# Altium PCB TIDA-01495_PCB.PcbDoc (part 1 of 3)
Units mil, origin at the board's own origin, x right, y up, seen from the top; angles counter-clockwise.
Board outline 7283.46 x 4330.71 mil, 2 copper layers (Top Layer, Bottom Layer), stack 64.6 mil thick; 242 components, 114 nets, 539 pads, 127 vias.
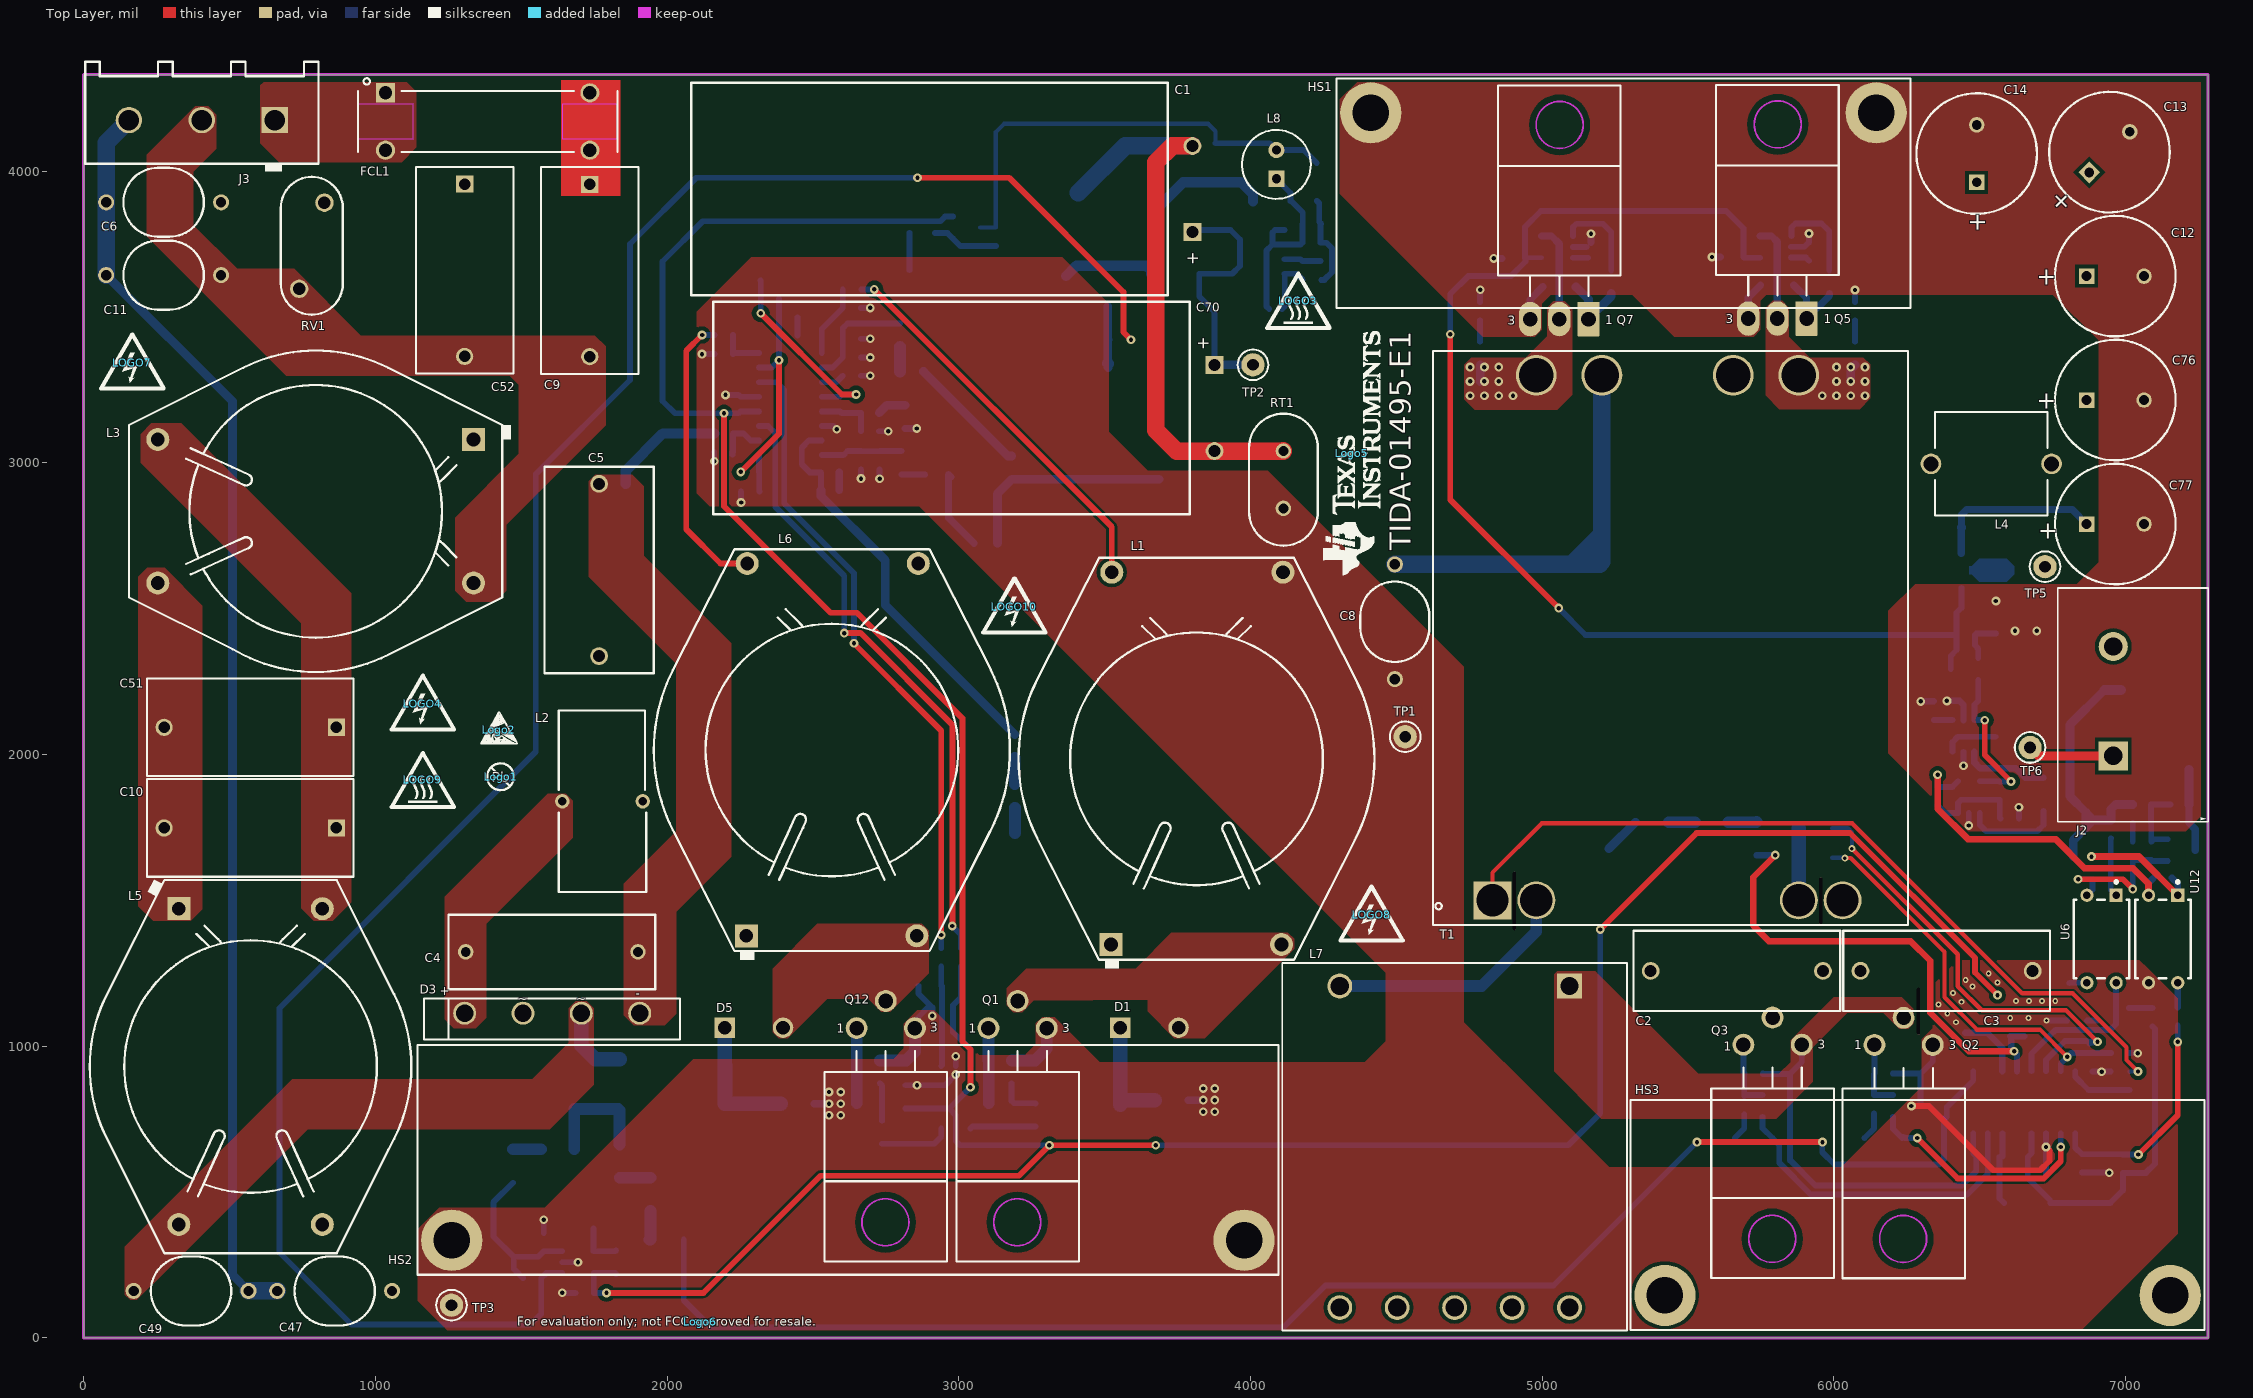
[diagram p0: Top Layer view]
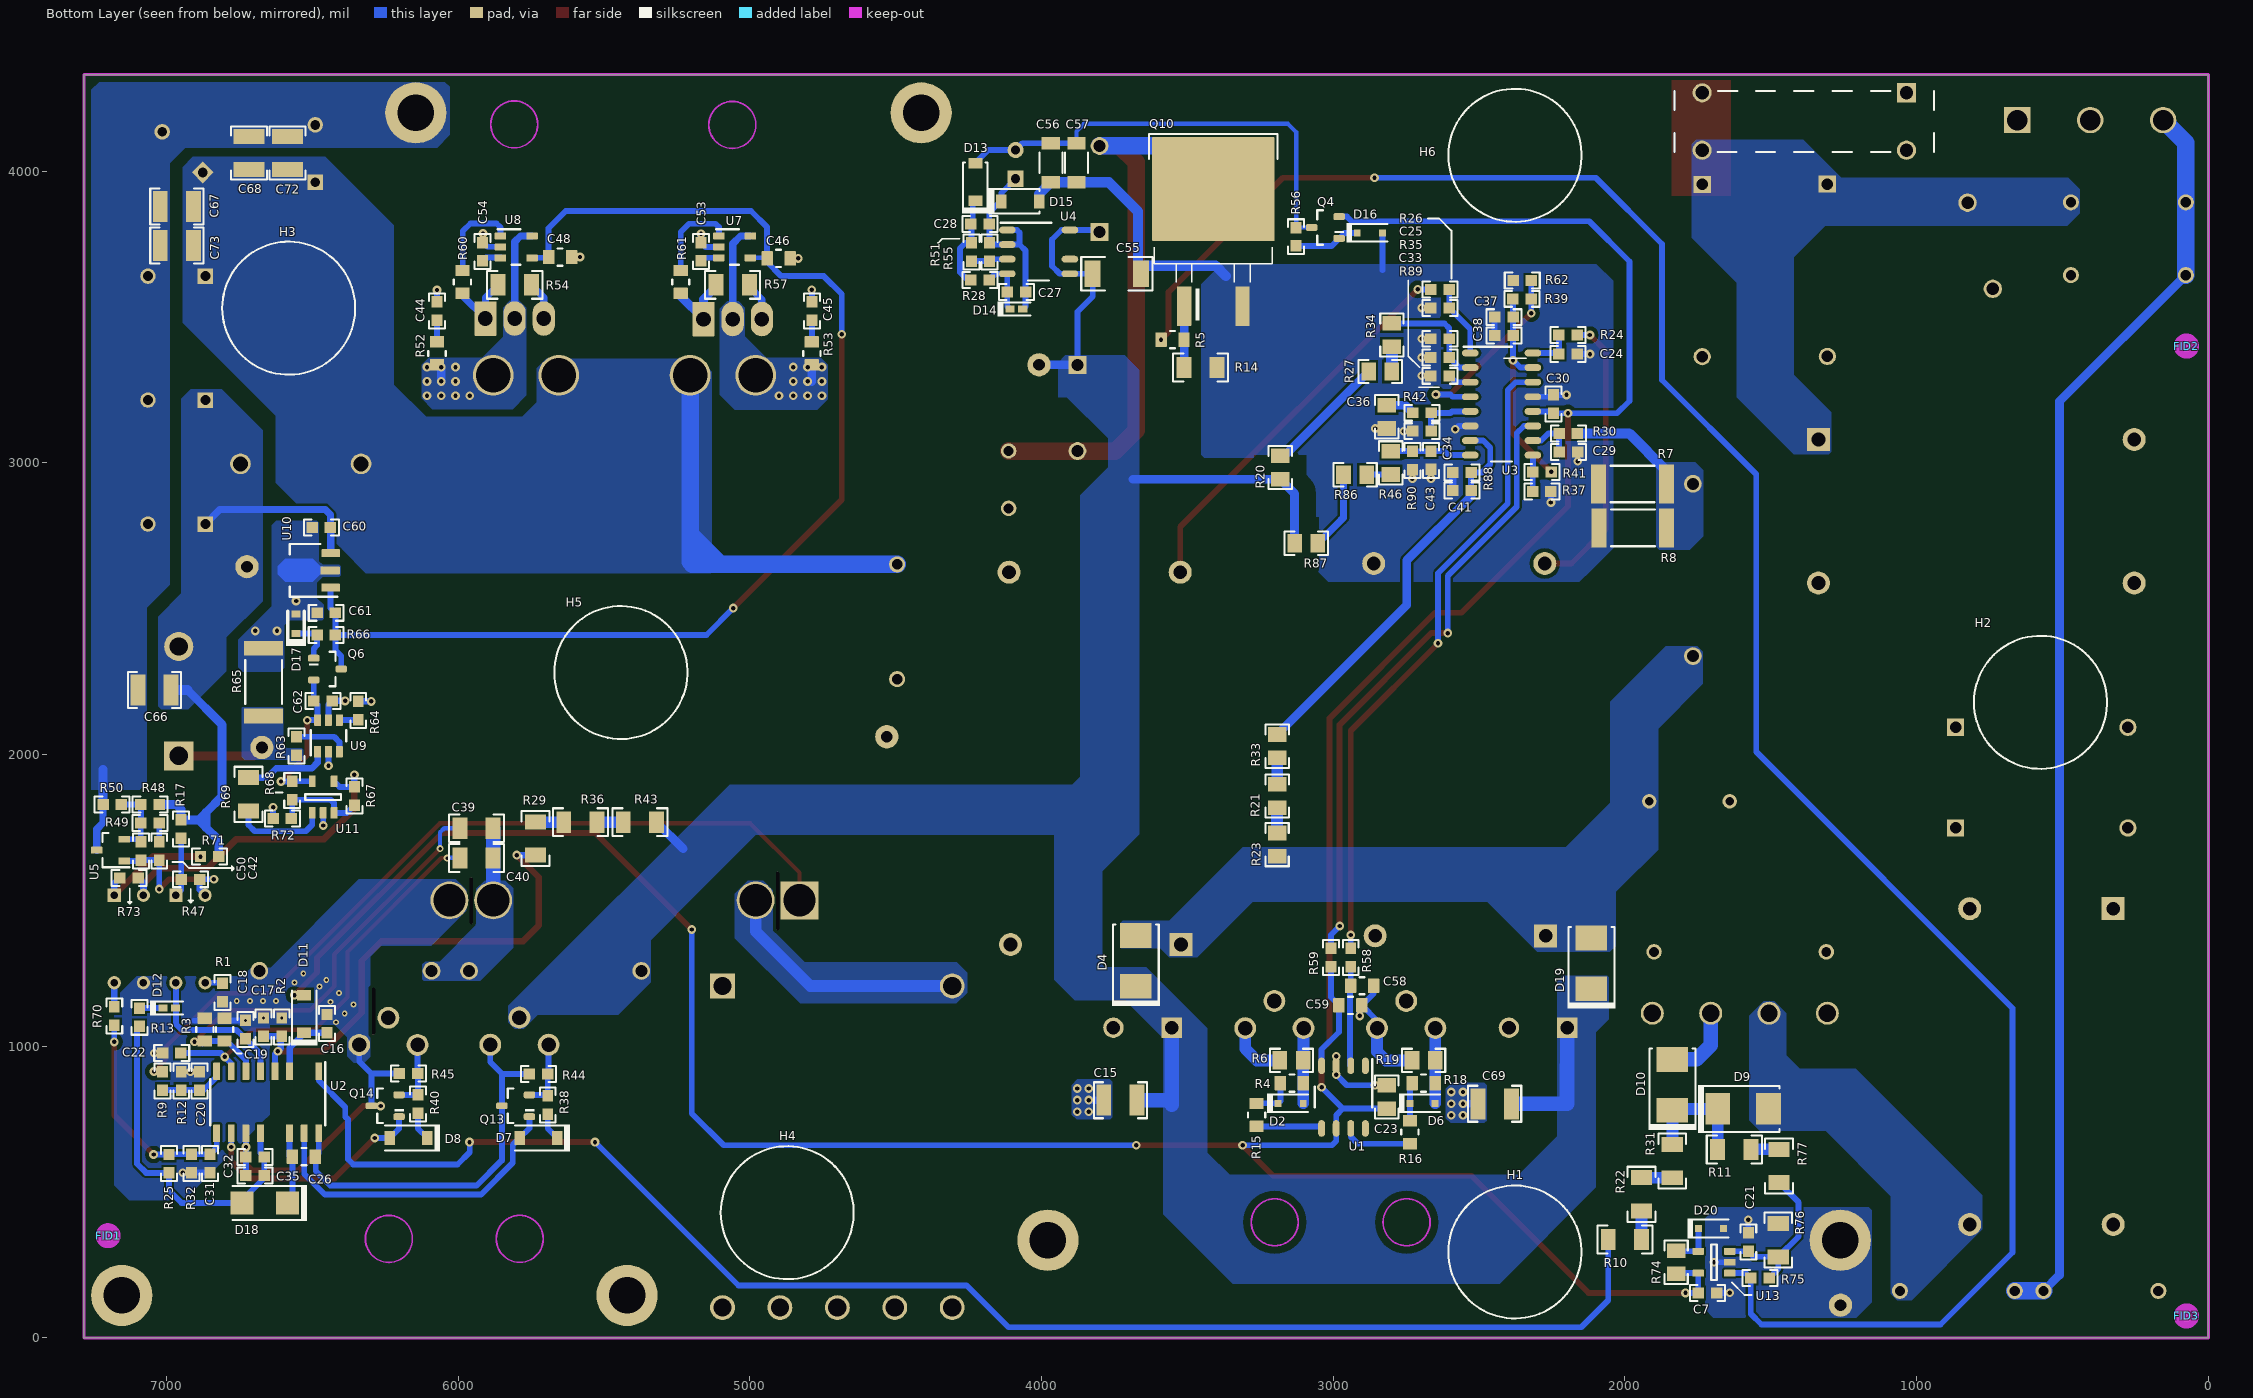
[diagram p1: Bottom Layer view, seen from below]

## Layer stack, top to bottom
Top Solder: solder mask 0.4, Solder Resist, Dk 3.5
Top Layer: signal copper 2.8
Dielectric1: core 59, FR-4 High Tg, Dk 4.8
Bottom Layer: signal copper 2.8
Bottom Solder: solder mask 0.4, Solder Resist, Dk 3.5

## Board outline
0,0 7283.46,0 7283.46,4330.71 0,4330.71

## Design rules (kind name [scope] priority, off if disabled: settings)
AcuteAngle [All] p1: minimum=4.50000000000000E+0001 checktracksonly=FALSE
AssemblyTestPointUsage [All] p1: valid=2
Clearance Clearance_1 [InNet('NetR10_2') vs InNet('PGND')] p1: gap=60 ignorepadtopadclearanceinfootprint=FALSE except(0: Arc-Hole Track-Hole SMDPad-Hole THPad-Hole Via-Hole Fill-Hole Poly-Hole Region-Hole Text-Hole)
Clearance Clearance_390V_Discrete [InNet('390V') vs InNet('NetR20_1') Or InNet('NetR86_2') Or InNet('NetQ3_1') Or InNet('SW') Or IsKeepOut] p2: gap=24 ignorepadtopadclearanceinfootprint=FALSE except(0: Arc-Hole Track-Hole SMDPad-Hole THPad-Hole Via-Hole Fill-Hole Poly-Hole Region-Hole Text-Hole)
Clearance Clearance_390V [InNet('390V')] p3: gap=59.05 ignorepadtopadclearanceinfootprint=FALSE except(0: Arc-Hole Track-Hole SMDPad-Hole THPad-Hole Via-Hole Fill-Hole Poly-Hole Region-Hole Text-Hole)
Clearance Clearance_MTG [InPadClass('MTG')] p4: gap=30 ignorepadtopadclearanceinfootprint=FALSE except(0: Arc-Hole Track-Hole SMDPad-Hole THPad-Hole Via-Hole Fill-Hole Poly-Hole Region-Hole Text-Hole)
Clearance Clearance_Keepouts [IsKeepOut] p5: gap=20 ignorepadtopadclearanceinfootprint=FALSE except(0: Arc-Hole Track-Hole SMDPad-Hole THPad-Hole Via-Hole Fill-Hole Poly-Hole Region-Hole Text-Hole; 19.5: Arc-SMDPad Track-SMDPad)
Clearance Clearance_Poly [InPolygon] p6: gap=15 ignorepadtopadclearanceinfootprint=FALSE except(0: Arc-Hole Track-Hole SMDPad-Hole THPad-Hole Via-Hole Fill-Hole Poly-Hole Region-Hole Text-Hole; 8: Track-Poly SMDPad-Poly; 12: THPad-Poly)
Clearance [All] p7: gap=7.7 ignorepadtopadclearanceinfootprint=FALSE except(0: Arc-Hole Track-Hole SMDPad-Hole THPad-Hole Via-Hole Fill-Hole Poly-Hole Region-Hole Text-Hole)
ComponentClearance ComponentClearance_MountingHoles_FiducialMarks [InComponentClass('Mounting Holes') vs InComponentClass('FiducialMark')] p1: gap=10 collisioncheckmode=3 verticalgap=10 showdistances=FALSE
ComponentClearance ComponentClearance_Shunt [InComponentClass('Header') vs InComponentClass('Shunt')] p2: gap=0 collisioncheckmode=3 verticalgap=0 showdistances=FALSE
ComponentClearance ComponentClearance_Logo [InComponentClass('Logo')] p3: gap=20 collisioncheckmode=3 verticalgap=10 showdistances=FALSE
ComponentClearance ComponentClearance_ScrewToNut [(HasFootprint('NY PMS 440 0025 PH')) vs (HasFootprint('Keystone_1902C'))] p4: gap=5 collisioncheckmode=3 verticalgap=10 showdistances=FALSE
ComponentClearance ComponentClearance_MountingHoles [InComponentClass('Mounting Holes')] p5: gap=50 collisioncheckmode=3 verticalgap=100000 showdistances=FALSE
ComponentClearance ComponentClearance_SmallPassives [HasFootprint('0201*') or HasFootprint('0402*') or HasFootprint('0508') or HasFootprint('0603*') or HasFootprint('0612') or HasFootprint('0805*') or HasFootprint('0815*') or HasFootprint('0830*') or HasFootprint('1206*') or HasFootprint('1210*') or HasFootprint('1808*') or HasFootprint('1812*') or HasFootprint('1825*') or HasFootprint('2010*') or HasFootprint('2220*') or HasFootprint('2225*') or HasFootprint('2512*') or HasFootprint('2728*') or HasFootprint('3518*') vs HasFootprint('0201*') or HasFootprint('0402*') or HasFootprint('0508') or HasFootprint('0603*') or HasFootprint('0612') or HasFootprint('0805*') or HasFootprint('0815*') or HasFootprint('0830*') or HasFootprint('1206*') or HasFootprint('1210*') or HasFootprint('1808*') or HasFootprint('1812*') or HasFootprint('1825*') or HasFootprint('2010*') or HasFootprint('2220*') or HasFootprint('2225*') or HasFootprint('2512*') or HasFootprint('2728*') or HasFootprint('3518*')] p6: gap=10 collisioncheckmode=3 verticalgap=10 showdistances=FALSE
ComponentClearance ComponentClearance_THtoSMT [IsThruComponent vs IsSMTComponent] p7: gap=5 collisioncheckmode=3 verticalgap=20 showdistances=FALSE
ComponentClearance ComponentClearance_THtoTH [IsThruComponent vs IsThruComponent] p8: gap=10 collisioncheckmode=3 verticalgap=10 showdistances=FALSE
ComponentClearance [All] p9: gap=10 collisioncheckmode=3 verticalgap=10 showdistances=FALSE
DiffPairsRouting [All] p1: maxlimit=100 minlimit=10 mostfreqgap=10 toplayer_minwidth=15 toplayer_maxwidth=15 toplayer_prefwidth=15 bottomlayer_minwidth=15 bottomlayer_maxwidth=15 bottomlayer_prefwidth=15 maxuncoupledlength=1000
FabricationTestPointUsage TestPointUsage [All] p1: valid=2 allowmultiple=FALSE
FabricationTestpoint Testpoint [All] p1: side=3 testpointundercomponent=TRUE minsize=40 maxsize=100 preferedsize=60 minholesize=0 maxholesize=40 preferedholesize=32 testpointgrid=1 allowsidetop=TRUE allowsidebottom=TRUE usegrid=TRUE gridtolerance=0.01
FanoutControl Fanout_LCC [IsLCC] p1: bgadir=Out bgaviamode=Centered fanoutstyle=Auto fanoutdirection=Alternating viagrid=1 // Fanout_LCC (Default Rule)
FanoutControl Fanout_BGA [IsBGA] p2: bgadir=Out bgaviamode=Centered fanoutstyle=Auto fanoutdirection=Alternating viagrid=1 // Fanout_BGA (Default Rule)
FanoutControl Fanout_Default [All] p4: bgadir=Out bgaviamode=Centered fanoutstyle=Auto fanoutdirection=Alternating viagrid=1 // Fanout_Default (Default Rule)
FanoutControl Fanout_Small [(CompPinCount < 5)] p5: bgadir=Out bgaviamode=Centered fanoutstyle=Auto fanoutdirection=OutThenIn viagrid=1 // Fanout_Small (Default Rule)
Height [All] p1: minheight=0 maxheight=2100 prefheight=500
HoleSize [All] p1: absolutevalues=TRUE maxlimit=251 minlimit=7.87 maxpercent=80.000 minpercent=20.000
MinimumAnnularRing MinimumAnnularRing_ThermalPadVias [IsVia and InAnyComponent] p1: minimumring=5.91
MinimumAnnularRing [All] p2: minimumring=5
MinimumSolderMaskSliver MinimumSolderMaskSliver_Logo [InComponentClass('Logo') vs InComponentClass('Logo')] p1: minsoldermaskwidth=0.7
MinimumSolderMaskSliver [All] p2: minsoldermaskwidth=3.94
PlaneConnect [All] p1: planeconnectstyle=Relief reliefexpansion=10 reliefentries=4 reliefconductorwidth=10 reliefairgap=10
PolygonConnect [All] p1: connectstyle=Direct reliefconductorwidth=10 reliefentries=4 polygonreliefangle="90 Angle" airgapwidth=10
RoutingVias [All] p1: holewidth=12 width=24 viastyle="Through Hole" minholewidth=7.87 minwidth=19.68 maxholewidth=40 maxwidth=65
RoutingVias ThermalPadVias [IsVia and InAnyComponent] p2: holewidth=7.87 width=19.68 viastyle="Through Hole" minholewidth=7.87 minwidth=19.68 maxholewidth=12.99 maxwidth=23.62
SilkToBoardRegionClearance [Not ((IsComment or IsDesignator) And (Hide <> 'False')) and not InRegion(1000,500,4000,800)] p1:
SilkToSilkClearance SilkToSilkClearance_Pb-FreeLogo [(HasFootprint('Pb-Free_Overlay_Medium') OR HasFootprint('Pb-Free_Overlay_Small')) vs (HasFootprint('Pb-Free_Overlay_Medium') OR HasFootprint('Pb-Free_Overlay_Small'))] p1: silktosilkclearance=0
SilkToSilkClearance [All] p2: silktosilkclearance=4
SilkToSolderMaskClearance SilkToComponentPadClearance [IsPad and InAnycomponent] p1: minsilkscreentomaskgap=5 clearancetoexposedcopper=TRUE
SilkToSolderMaskClearance "Silk to Solder Mask Opening" [All] p2: minsilkscreentomaskgap=4 clearancetoexposedcopper=FALSE
SolderMaskExpansion [All] p1: expansion=2.5
Width [All] p1: maxlimit=100 minlimit=6 preferedwidth=10 checkconnectedcopper=TRUE
14 further rules are at their usual default settings.

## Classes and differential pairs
component class AssemblyNote: ZZ1 ZZ2 ZZ3 ZZ4
component class FiducialMark: FID1 FID2 FID3
component class TIDA-01495_Hardware: FID1 FID2 FID3 H1 H2 H3 H4 H5 H6 Logo1 Logo2 LOGO3 LOGO4 Logo5 Logo6 LOGO7 LOGO8 LOGO9 LOGO10 ZZ1 ZZ2 ZZ3 ZZ4
component class Logo: Logo5
component class TIDA-01495-LLC: C2 C3 C8 C12 C13 C14 C16 C17 C18 C19 C20 C22 C26 C31 C32 C35 C39 C40 C42 C44 C45 C46 C48 C50 C53 C54 C60 C61 C62 C66 C67 C68 C72 C73 C76 C77 D7 D8 D11 D12 D17 D18 HS1 HS3 J2 L4 L7 Q2 Q3 Q5 Q6 Q7 Q13 Q14 R1 R2 R3 R9 R10 R12 R13 R17 R22 R25 R29 R31 R32 R36 R38 R40 R43 R44 R45 R47 R48 R49 R50 R52 R53 R54 R57 R60 R61 R63 R64 R65 R66 R67 R68 R69 R70 R71 R72 R73 T1 TP1 TP5 TP6 U2 U5 U6 U7 U8 U9 U10 U11 U12
component class TIDA-01495_PFC: C1 C4 C5 C6 C7 C9 C10 C11 C15 C21 C23 C24 C25 C27 C28 C29 C30 C33 C34 C36 C37 C38 C41 C43 C47 C49 C51 C52 C55 C56 C57 C58 C59 C69 C70 D1 D2 D3 D4 D5 D6 D9 D10 D13 D14 D15 D16 D19 D20 FCL1 HS2 J3 L1 L2 L3 L5 L6 L8 Q1 Q4 Q10 Q12 R4 R5 R6 R7 R8 R11 R14 R15 R16 R18 R19 R20 R21 R23 R24 R26 R27 R28 R30 R33 R34 R35 R37 R39 R41 R42 R46 R51 R55 R56 R58 R59 R62 R74 R75 R76 R77 R86 R87 R88 R89 R90 RT1 RV1 TP2 TP3 U1 U3 U4 U13
net class HV: 390V NetC2_2 NetC4_1 NetD1_3 NetD5_3 NetL7_2 NetR10_2 NetR20_1 NetR21_2 NetR86_2 SW VAC

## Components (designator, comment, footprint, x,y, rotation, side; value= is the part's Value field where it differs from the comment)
C1 "450BXW150MEFC18X45" KXG_1800X4000_HORIZONTALDOWN 3801.29,3938.37 r270 top value=150uF
C2 "B32642B0333J" B32652_1800x700x1250 5667.44,1258.06 r0 top value=0.033uF
C3 "B32642B0333J" B32652_1800x700x1250 6386.48,1258.16 r0 top value=0.033uF
C4 "450MPK474J" MPK_1800x650 1605,1323 r0 top value=0.47uF
C5 "450MPK105J" MPK_1800x950 1766.95,2632.53 r270 top value=1uF
C6 "AY2222M35Y5US63L7" CD45_700x600x1100 274,3893 r180 top value=2200pF
C7 "EMK107B7104KA-T" 0603 1717,154 r180 bottom value=0.1uF
C8 "AY2222M35Y5US63L7" CD45_700x600x1100 4495,2455 r270 top value=2200pF
C9 "B32922C3334K" B32922_14.5mm 1735,3659 r270 top value=0.33uF
C10 "B32922C3334K" B32922_14.5mm 571,1748 r180 top value=0.33uF
C11 "AY2222M35Y5US63L7" CD45_700x600x1100 274,3643.15 r0 top value=2200pF
C12 "35ZLH330MEFC10X12.5" Chemi-Con_1000x2000 6965,3640 r0 top value=330uF
C13 "35ZLH330MEFC10X12.5" Chemi-Con_1000x2000 6945,4065 r45 top value=330uF
C14 "35ZLH330MEFC10X12.5" Chemi-Con_1000x2000 6490,4060 r90 top value=330uF
C15 "VJ1210Y471KXEAT5Z" 1210 3729.56,814.56 r0 bottom value=470pF
C16 "0603ZD475KAT2A" 0603 6450,1077 r90 bottom value=4.7uF
C17 "06031C103JAT2A" 0603 6667,1065 r270 bottom value=0.01uF
C18 "C0603C101J5GAC" 0603 6729.53,1056.52 r90 bottom value=100pF
C19 "08055A3R3CAT2A" 0805_HV1 6801,1057 r90 bottom value=3.3pF
C20 "06035A100JAT2A" 0603 6886.38,881.04 r90 bottom value=10pF
C21 "EMK107B7104KA-T" 0603 1577,328 r90 bottom value=0.1uF
C22 "GRM188R71H682KA01D" 0603 6982,976 r0 bottom value=6800pF
C23 "0805YD225KAT2A" 0805_HV 2816.34,825.95 r90 bottom value=2.2uF
C24 "C0603C220J5GACTU" 0603 2194.93,3372.69 r180 bottom value=22pF
C25 "C0603C220J5GACTU" 0603 2633.73,3530.93 r0 bottom value=22pF
C26 "C0805C104K1RACTU" 0805_HV1 6529,621 r180 bottom value=0.1uF
C27 "C1608X5R1A106M" 0603 4086,3585 r180 bottom value=10uF
C28 "0603YC104JAT2A" 0603 4211,3819 r180 bottom value=0.1uF
C29 "C1608X7R1H102K" 0603 2193.11,3036.39 r180 bottom value=1000pF
C30 "GRM188R71E105KA12D" 0603 2245.41,3201.14 r90 bottom value=1uF
C31 "06033D224KAT2A" 0603 6850.46,597.77 r270 bottom value=0.22uF
C32 "GRM188R72A104KA35J" 0603 6696.34,620.01 r0 bottom value=0.1uF
C33 "C1608X7R1H102K" 0603 2633.82,3361.06 r0 bottom value=1000pF
C34 "06035A821JAT2A" 0603 2695.41,3108.33 r0 bottom value=820pF
C35 "0603ZD475KAT2A" 0603 6696.44,556.99 r0 bottom value=4.7uF
C36 "0805YD225KAT2A" 0805_HV 2816.35,3157.62 r270 bottom value=2.2uF
C37 "UMK107AB7105KA-T" 0603 2415.17,3499.14 r0 bottom value=1uF
C38 "EMK107B7104KA-T" 0603 2415.17,3436.5 r0 bottom value=0.1uF
C39 "GRM31A7U3A151JW31D" 1206 5937.28,1747 r0 bottom value=150pF
C40 "GRM31A7U3A151JW31D" 1206 5937.28,1645.3 r0 bottom value=150pF
C41 "06031C102MAT2A" 0603 2559.09,2905.14 r0 bottom value=1000pF
C42 "GRM188R71C473KA01D" 0603 7024.99,1669.6 r270 bottom value=0.047uF
C43 "GRM188R71H681KA01D" 0603 2664.81,3008.54 r270 bottom value=680pF
C44 "GRM1885C2A331JA01D" 0603 6072.63,3519.92 r270 bottom value=330pF
C45 "GRM1885C2A331JA01D" 0603 4787.51,3520.02 r270 bottom value=330pF
C46 "C0805C105K3RACTU" 0805_HV1 4901.4,3700.57 r180 bottom value=1uF
C47 "DE2E3KY222MA2BM01" CD45_700x600x1100 860.28,160.67 r180 top value=2200pF
C48 "C0805C105K3RACTU" 0805_HV1 5650.72,3705.36 r180 bottom value=1uF
C49 "DE2E3KY222MA2BM01" CD45_700x600x1100 368.12,160.67 r180 top value=2200pF
C50 "06035A100JAT2A" 0603 7087.99,1669.6 r270 bottom value=10pF
C51 "B32922C3334K" B32922_14.5mm 571,2093 r180 top value=0.33uF
C52 "B32922C3334K" B32922_14.5mm 1306,3660 r270 top value=0.33uF
C53 "C1608X6S1C225K080AC" 0603 5167.61,3723.64 r90 bottom value=2.2uF
C54 "C1608X6S1C225K080AC" 0603 5916,3723.64 r90 bottom value=2.2uF
C55 "VJ1808Y103KBLAT4X" 1808 3742,3648 r180 bottom value=0.01uF
C56 "C3216X5R1V226M160AC" 1206_180 3968,4028.43 r270 bottom value=22uF
C57 "C3216X5R1V226M160AC" 1206_180 3880.32,4028.43 r270 bottom value=22uF
C58 "08055A101JAT2A" 0805_HV1 2901,1207 r180 bottom value=100pF
C59 "08055A101JAT2A" 0805_HV1 2941,1140 r180 bottom value=100pF
C60 "GRM188R71E105KA12D" 0603 6469.26,2777.84 r0 bottom value=1uF
C61 "GRM188R71E105KA12D" 0603 6452.38,2485.72 r0 bottom value=1uF
C62 "GRM188R71E105KA12D" 0603 6463.53,2183.57 r180 bottom value=1uF
C66 "C3225X7S2A475K200AE" 1210 7041,2221 r0 bottom value=4.7uF
C67 "C3225X7S2A475K200AE" 1210 6964.44,3879.15 r0 bottom value=4.7uF
C68 "C3225X7S2A475K200AE" 1210 6717.47,4062.05 r90 bottom value=4.7uF
C69 "VJ1210Y471KXEAT5Z" 1210 2446.57,802.49 r0 bottom value=470pF
C70 "450BXW150MEFC18X45" KXG_1800x4000_horizontalDown 3877,3187.94 r270 top value=150uF
C72 "C3225X7S2A475K200AE" 1210 6585.37,4062.05 r90 bottom value=4.7uF
C73 "C3225X7S2A475K200AE" 1210 6964.44,3745.45 r0 bottom value=4.7uF
C76 "35ZLH330MEFC10X12.5" Chemi-Con_1000x2000 6965,3215 r0 top value=330uF
C77 "35ZLH330MEFC10X12.5" Chemi-Con_1000x2000 6965,2790 r0 top value=330uF
D1 "MUR860G" TO-220AC_HORIZ 3653.7,1063.35 r180 top value=0.98V
D2 "BAT54HT1G" sod-323 3146,804 r180 bottom value=0.35V
D3 "GBU8J" GBU 1606,1112.85 r0 top
D4 "RS1MB-13-F" SMB 3676.72,1292.22 r90 bottom value=1000V
D5 "MUR860G" TO-220AC_HORIZ 2297.66,1063.35 r180 top value=0.98V
D6 "BAT54HT1G" sod-323 2694,804 r180 bottom value=0.35V
D7 "SD103BW-7-F" SOD-123 5725,685 r0 bottom value=30V
D8 "SD103BW-7-F" SOD-123 6170,685 r0 bottom value=30V
D9 "RS1MB-13-F" SMB 1594.68,784.65 r180 bottom value=1000V
D10 "RS1MB-13-F" SMB 1836.97,867.36 r90 bottom value=1000V
D11 "SD103BW-7-F" SOD-123 6528,1110 r90 bottom value=30V
D12 "BZT52C6V2T-7" SOD-523 6990.8,1130.97 r180 bottom value=6.2V
D13 "UFM15PL-TP" SOD-123FL 4227.09,3962.99 r90 bottom value=600V
D14 "5.61V" SOD-523 4086,3527 r180 bottom
D15 "UFM15PL-TP" SOD-123FL 4073.11,3896.42 r180 bottom value=600V
D16 "BZX384-C15,115" sod-323 2874.34,3788.33 r180 bottom value=15V
D17 "CZRU52C5V6" SOD-523F 6555.94,2447.67 r90 bottom value=5.6V
D18 "US1J-13-F" SMA 6663.13,461.95 r0 bottom value=600V
D19 "RS1MB-13-F" SMB 2114.75,1283.9 r90 bottom value=1000V
D20 "BZT52C5V1S-7-F" SOD-323 1705,375 r180 bottom value=5.1V
FCL1 "01110501Z" LITTELFUSE_01110501Z 1385,4170 r0 top
FID1 "Fiducial" Fiducial10-20 7200,350 r90 bottom
FID2 "Fiducial" Fiducial10-20 75,3400 r90 bottom
FID3 "Fiducial" Fiducial10-20 75,75 r90 bottom
H1 "SJ-5303 (CLEAR)" Bumpon_SJ5003Transparent 2377.04,294.33 r180 bottom
H2 "SJ-5303 (CLEAR)" Bumpon_SJ5003Transparent 575.26,2178.84 r180 bottom
H3 "SJ-5303 (CLEAR)" Bumpon_SJ5003Transparent 6581,3530 r180 bottom
H4 "SJ-5303 (CLEAR)" Bumpon_SJ5003Transparent 4871.88,429.01 r180 bottom
H5 "SJ-5303 (CLEAR)" Bumpon_SJ5003Transparent 5442.2,2280.87 r180 bottom
H6 "SJ-5303 (CLEAR)" Bumpon_SJ5003Transparent 2377.04,4054.17 r180 bottom
HS1 "782653B04250G" HEATSINK_782653B04250G 5279,3924 r180 top
HS2 "" "HEATSINK_782653B04250G - DUPLICATE1" 2620,610 r0 top locked
HS3 "782653B04250G" HEATSINK_782653B04250G 6287,421 r0 top
J2 "OSTT7022150" TERM_BLK_OSTT7022150 6958,1995 r90 top
J3 "350429-1" TE_350429-1 405,4175 r180 top
L1 "Custom" WE-CMBH_UPDATED 3815,1985 r0 top value="150 µH"
L2 "7447076" IND_7447020 1778.73,1839.34 r0 top value=150uH
L3 "744834433" WE-CMBH 795.32,2833.59 r270 top value=3.3mH
L4 "THCBR1290-231IN" THCBR1290 6539.72,2996.32 r0 top value=230nH
L5 "744834433" WE-CMBH 572,930 r0 top value=3.3mH
L6 "Custom" WE-CMBH_UPDATED 2565,2015 r0 top value="150 µH"
L7 "" IND_CUST 4700,655 r270 top
L8 "744741222" WE-TI_5075 4089,4023 r90 top value=1mH
Logo1 "Pb-Free Symbol" Pb-Free_Overlay_Small 1429.03,1923.53 r0 top
Logo2 "ESD Susceptible" ESD_Overlay_Small 1423.26,2085.14 r0 top
LOGO3 "CAUTION HOT SURFACE" IEC_HotSurface_Small 4164.13,3555.69 r0 top
LOGO4 "DANGER HIGH VOLTAGE" IEC_HighVoltage_Small 1162.87,2173.3 r0 top
Logo5 "Texas Instruments" TI_Stacked_Overlay_Small 4347.41,3033.32 r90 top
Logo6 "FCC disclaimer" FCC_disclaimer 2113.18,55.26 r0 top
LOGO7 "DANGER HIGH VOLTAGE" IEC_HighVoltage_Small 166.83,3343.01 r0 top
LOGO8 "DANGER HIGH VOLTAGE" IEC_HighVoltage_Small 4415.11,1450.1 r0 top
LOGO9 "CAUTION HOT SURFACE" IEC_HotSurface_Small 1162.87,1912.8 r0 top
LOGO10 "DANGER HIGH VOLTAGE" IEC_HighVoltage_Small 3190.93,2506.42 r0 top
Q1 "IPP60R190P6" TO-220AB_HORIZONTAL#1 3201.76,1061.85 r180 top value=650V
Q2 "STP24N60M2" TO-220AB_HORIZONTAL#1 6239.29,1004.25 r180 top value=650V
Q3 "STP24N60M2" TO-220AB_HORIZONTAL#1 5790,1005 r180 top value=650V
Q4 "BC848CLT1G" SOT-23 3026.96,3806.59 r0 bottom value="30 V"
Q5 "CSD19536KCS" TO-220AB_HORIZONTAL#2 5806.6,3494.47 r0 top value=100V
Q6 "MMBT2222LT1G" SOT-23 6447.96,2292.77 r180 bottom value="30 V"
Q7 "CSD19536KCS" TO-220AB_HORIZONTAL#2 5058.88,3492.68 r0 top value=100V
Q10 "STB45N65M5" DDPAK 3411,3783 r90 bottom value=650V
Q12 "IPP60R190P6" TO-220AB_HORIZONTAL#1 2749.75,1061.85 r180 top value=650V
Q13 "BC858C-7-F" SOT-23 5802.93,795.57 r0 bottom value="30 V"
Q14 "BC858C-7-F" SOT-23 6250.03,795.57 r0 bottom value="30 V"
R1 "RNCF0603TKY10K0" 0603 6807.54,1184.25 r90 bottom value=10k
R2 "RNCF0603TKY10K0" 0603 6605,1065 r270 bottom value=10k
R3 "CRCW0805162RFKEA" 0805_HV1 6868.53,1057 r270 bottom value=162
R4 "CRCW080518R2FKEA" 0805_HV1 3142,873 r180 bottom value=18.2
R5 "CRCW080518R2FKEA" 0805_HV1 3551,3422 r0 bottom value=18.2
R6 "CRCW080510K0FKEA" 0805_HV 3142.76,951 r180 bottom value=10.0k
R7 "CSRN2512FK30L0" 2512 1974.23,2927.3 r180 bottom value=0.03
R8 "CSRN2512FK30L0" 2512 1972.98,2776.92 r180 bottom value=0.03
R9 "RT0603DRE0770K6L" 0603 7014.06,881.04 r90 bottom value=70.6k
R10 "CRCW12061K00FKEA" 1206 2000,337 r0 bottom value=1.00k
R11 "CRCW1206511KFKEA" 1206 1625,646 r180 bottom value=511k
R12 "CRCW060310K0FKEA" 0603 6949.52,881.04 r270 bottom value=10.0k
R13 "RNCF0603TKY10K0" 0603 7093,1099 r90 bottom value=10k
R14 "CRCW120649K9FKEA" 1206 3455,3327 r0 bottom value=49.9k
R15 "CRCW08052R20JNEA" 0805_HV1 3263,764 r90 bottom value=2.2
R16 "CRCW08052R20JNEA" 0805_HV1 2737,705 r90 bottom value=2.2
R17 "CRCW06036K04FKEA" 0603 6950,1744 r90 bottom value=6.04k
R18 "CRCW080518R2FKEA" 0805_HV1 2690,873 r180 bottom value=18.2
R19 "CRCW080510K0FKEA" 0805_HV 2690,951 r180 bottom value=10.0k
R20 "CRCW08053M01FKEA" 0805_HV 3181.79,2983.49 r270 bottom value=3.01Meg
R21 "CRCW08052M87FKEA" 0805_HV 3191.96,1857.66 r270 bottom value=2.87Meg
R22 "CRCW12061K00FKEA" 1206 1943,492 r270 bottom value=1.00k
R23 "CRCW08052M87FKEA" 0805_HV 3192.54,1690.72 r270 bottom value=2.87Meg
R24 "CRCW060316K5FKEA" 0603 2195.17,3437.96 r0 bottom value=16.5k
R25 "CRCW0603750KFKEA" 0603 6991,597 r270 bottom value=750k
R26 "CRCW060316K5FKEA" 0603 2634.13,3594.32 r0 bottom value=16.5k
R27 "CRCW08052M74FKEA" 0805_HV 2838.72,3312.87 r0 bottom value=2.74Meg
R28 "CRCW06032K20JNEA" 0603 4211,3627 r0 bottom value=2.2k
R29 "CRCW1206330KJNEA" 1206 5735,1712 r90 bottom value=330k
R30 "CRCW0603100RFKEA" 0603 2194.21,3100.8 r0 bottom value=100
R31 "CRCW12061K00FKEA" 1206 1838,606 r270 bottom value=1.00k
R32 "CRCW0603487KFKEA" 0603 6914.46,597.77 r90 bottom value=487k
R33 "CRCW08052M87FKEA" 0805_HV 3191.96,2028.31 r270 bottom value=2.87Meg
R34 "CRCW08052M74FKEA" 0805_HV 2798.83,3437.96 r270 bottom value=2.74Meg
R35 "CRCW0603133KFKEA" 0603 2633.65,3425.09 r180 bottom value=133k
R36 "CRCW1206330KJNEA" 1206 5581,1768 r180 bottom value=330k
R37 "CRCW0603100KJNEA" 0603 2285,2902 r180 bottom value=100k
R38 "CRCW060322R0JNEA" 0603 5692.93,797.97 r90 bottom value=22
R39 "CRCW0603100KJNEA" 0603 2352.45,3562.07 r180 bottom value=100k
R40 "CRCW060322R0JNEA" 0603 6137.78,801.11 r90 bottom value=22
R41 "CRCW0603100KJNEA" 0603 2284.31,2968.64 r180 bottom value=100k
R42 "CRCW06037K50FKEA" 0603 2695.78,3171.38 r0 bottom value=7.50k
R43 "CRCW1206374KFKEA" 1206 5377,1768 r180 bottom value=374k
R44 "CR0603-JW-472GLF" 0603 5725,904 r180 bottom value=4.7k
R45 "CR0603-JW-472GLF" 0603 6170.78,905.97 r180 bottom value=4.7k
R46 "CRCW08052M74FKEA" 0805_HV 2803.32,2999.85 r270 bottom value=2.74Meg
R47 "CRCW06036K04FKEA" 0603 6918,1572 r0 bottom value=6.04k
R48 "CRCW0603147KFKEA" 0603 7055.99,1828.6 r180 bottom value=147k
R49 "CRCW060310K0FKEA" 0603 7056.23,1765.04 r0 bottom value=10.0k
R50 "CRCW060316K9FKEA" 0603 7186.07,1828.83 r180 bottom value=16.9k
R51 "CRCW0603100KJNEA" 0603 4240,3723 r270 bottom value=100k
R52 "CRCW080510R0JNEA" 0805_HV1 6072.63,3374.85 r90 bottom value=10
R53 "CRCW080510R0JNEA" 0805_HV1 4787.51,3374.95 r90 bottom value=10
R54 "RC1206FR-074K7L" 1206 5806,3610 r180 bottom value=4.70k
R55 "CRCW060312K0JNEA" 0603 4178,3723 r270 bottom value=12k
R56 "RT0603BRD0747KL" 0603 3127.24,3774.96 r90 bottom value=47.0k
R57 "RC1206FR-074K7L" 1206 5059,3610 r180 bottom value=4.70k
R58 "CRCW060310R0FKEAHP" 0603 2940,1304 r270 bottom value=10.0
R59 "CRCW060310R0FKEAHP" 0603 3008,1304 r270 bottom value=10.0
R60 "CRCW08054R70JNEA" 0805_HV1 5985.25,3619.78 r90 bottom value=4.7
R61 "CRCW08054R70JNEA" 0805_HV1 5236.84,3619.78 r270 bottom value=4.7
R62 "CRCW0603100KJNEA" 0603 2352.01,3625.24 r180 bottom value=100k
R63 "RC0603FR-0710RL" 0603 6554,2029 r90 bottom value=10.0
R64 "RC0603FR-0710RL" 0603 6342.6,2150.39 r270 bottom value=10.0
R65 "ERJ-M1WTF1M0U" 2512 6667,2248 r270 bottom value=0.001
R66 "CRCW060310K0FKEA" 0603 6452.37,2409.62 r0 bottom value=10.0k
R67 "MCT06030C1004FP500" 0603 6355.81,1857.32 r90 bottom value=1.00Meg
R68 "MCT06030C1004FP500" 0603 6569,1876 r90 bottom value=1.00Meg
R69 "CRCW1206330KJNEA" 1206 6718.84,1863.42 r90 bottom value=330k
R70 "CRCW0603487KFKEA" 0603 7178.95,1102.81 r270 bottom value=487k
R71 "CRCW06036K04FKEA" 0603 6851.92,1649.82 r180 bottom value=6.04k
R72 "RNCF0603TKY10K0" 0603 6603,1780 r180 bottom value=10k
R73 "CRCW06036K04FKEA" 0603 7128,1577 r0 bottom value=6.04k
R74 "CRCW080510K0FKEA" 0805_HV 1824.61,259.23 r270 bottom value=10.0k
R75 "CRCW06031M10FKEA" 0603 1537.11,204.88 r0 bottom value=1.10Meg
R76 "CRCW120649K9FKEA" 1206 1474.12,334.9 r270 bottom value=49.9k
R77 "CRCW1206511KFKEA" 1206 1472,589 r270 bottom value=511k
R86 "CRCW08052M74FKEA" 0805_HV 2924.83,2958.96 r0 bottom value=2.74Meg
R87 "CRCW08052M74FKEA" 0805_HV 3092.4,2724.21 r0 bottom value=2.74Meg
R88 "CRCW0603133KFKEA" 0603 2559.09,2967.14 r180 bottom value=133k
R89 "CRCW060366K5FKEA" 0603 2633.82,3298.06 r180 bottom value=66.5k
R90 "CRCW060382K5FKEA" 0603 2728.62,3008.25 r90 bottom value=82.5k
RT1 "B57236S0100M000" THERM_B57236S0 4113,2942 r90 top value="10 ohm"
RV1 "S10K275E2" VAR_S10K275E2 782,3744 r90 top
T1 "58599" WE_750343661_CUS 5430,2500 r90 top locked
TP1 "5001" Keystone5001 4530.41,2060.88 r0 top value=Black
TP2 "5000" Keystone5000 4008.63,3335.64 r90 top value=Red
TP3 "5001" Keystone5001 1260.86,112.12 r90 top value=Black
TP5 "5000" Keystone5000 6724,2644 r90 top value=Red
TP6 "5001" Keystone5001 6672.83,2023.89 r90 top value=Black
U1 "UCC27524AD" D0008A_N 2964.94,825.18 r270 bottom
U2 "UCC25630DDB" DDB0014A 6652.97,807.63 r270 bottom
U3 "UCC28063DR" D0016A_N 2422.82,3201.17 r180 bottom
U4 "UCC28880DR" D0007A_N 4010,3723 r180 bottom
U5 "TL431ACDBZR" DBZ0003A_N 7192,1672 r0 bottom
U6 "VO618A" DIP-4 6917.88,1367.31 r270 top
U7 "UCC24612-1DBVR" DBV0005A_N 5052.24,3740.06 r180 bottom
U8 "UCC24612-1DBVR" DBV0005A_N 5801,3740 r180 bottom
U9 "INA181A3IDBV" DBV0006A_N 6444.73,2063.49 r90 bottom
U10 "UA78L05CPK" PK0003A_M 6438.26,2630.84 r0 bottom
U11 "TL331IDBVR" DBV0005A_N 6462.82,1853.77 r90 bottom
U12 "VO618A" DIP-4 7128.98,1367.31 r270 top
U13 "TLV171IDBVR" DBV0005A_N 1694.61,259.23 r0 bottom
ZZ1 "This Assembly Note is for PCB labels only" AssemblyNoteLabel 749.99,5813.13 r0 top
ZZ2 "These assemblies are ESD sensitive, ESD precautions shall be observed." AssemblyNote 660.01,5722.41 r0 top
ZZ3 "These assemblies must be clean and free from flux and all contaminants. Use of no clean flux is not acceptable." AssemblyNote 660.01,5633.14 r0 top
ZZ4 "These assemblies must comply with workmanship standards IPC-A-610 Class 2, unless otherwise specified." AssemblyNote 660.01,5543.87 r0 top

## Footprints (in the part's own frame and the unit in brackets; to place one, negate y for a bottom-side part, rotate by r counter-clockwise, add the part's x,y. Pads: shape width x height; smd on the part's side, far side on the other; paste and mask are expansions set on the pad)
0603 [mm] "0603 from SM-752 data"
  rect 1x0.95 smd: 1(-0.8,0) 2(0.8,0)
  silkscreen extent -1.52,-0.69 1.52,0.69, body extent -0.87,-0.47 0.87,0.47, height 1
0805_HV [mil] "0805 with 30mil clearance between pads"
  rect 50x63 smd: 1(-40,0) 2(40,0)
  silkscreen extent -74,-40 74,40, body extent -43,-29 43,29, height 57
0805_HV1 [mm] "Custom footprint based on analyzing multiple manufacturer recommendations"
  rrect10% 1x1.25 smd: 1(-1,0) 2(1,0)
  silkscreen extent -0.2,-0.75 0.2,0.75, body extent -1.1,-0.72 1.1,0.73, height 1.45
1206 [mm] "1206 from SM-752 data"
  rect 1.3x1.85 smd: 1(-1.45,0) 2(1.45,0)
  silkscreen extent -2.4,-1.21 2.4,1.21, body extent -1.7,-0.9 1.7,0.9, height 1.35
1206_180 [mm] "1206_180"
  rect 1.1x1.6 smd: 1(-1.7,0) 2(1.7,0)
  silkscreen extent -0.9,-1 0.9,1, body extent -1.75,-0.95 1.75,0.95, height 1.8
1210 [mm] "1210 from SM-752 data"
  rect 1.3x2.7 smd: 1(-1.45,0) 2(1.45,0)
  silkscreen extent -2.32,-1.57 2.32,1.57, body extent -1.7,-1.35 1.7,1.35, height 1.35
1808 [mm] "Chip Capacitor, Body 4.6x2.0mm, IPC Medium Density"
  rect 1.4x2.3 smd: 1(-2.1,0) 2(2.1,0)
  silkscreen extent -3.1,-1.45 3.1,1.45, body extent -2.47,-1.2 2.47,1.2, height 2.03
2512 [mm] "Chip Resistor, Body 6.3x3.2mm, IPC Medium Density"
  rect 1.3x3.4 smd: 1(-2.95,0) 2(2.95,0)
  silkscreen extent -1.9,-1.6 1.9,1.6, body extent -3.22,-1.67 3.22,1.67, height 0.71
AssemblyNote [mil] "Assembly Note"
AssemblyNoteLabel [mil] "Assembly Note for PCB Labels"
B32652_1800x700x1250 [mm] "TH, 2-Leads, Body 18x7mm, Pin Spacing 15mm"
  round 1.55 hole 1.05: 1(-7.5,0) 2(7.5,0)
  silkscreen extent -9,-3.5 9,3.5, body extent -9,-3.5 9,3.5, height 12.5
B32922_14.5mm [mm] "Epcos film capacitors, 15mm spacing"
  rect 1.5x1.5 hole 1: 1(-7.5,0)
  round 1.5 hole 1: 2(7.5,0)
  silkscreen extent -9,-4.25 9,4.25, body extent -9,-4.25 9,4.25, height 14.5
Bumpon_SJ5003Transparent [mil] "3M Hemispherical Bumpon transparent"
  round 1 on Mech4: 0(0,0)
  silkscreen extent -228,-228 228,228, body extent -219,-219 219,219, height 197
CD45_700x600x1100 [mm] "TH, 2-Leads, Dia 7mm, Pin Spacing 10 mm"
  round 1.4 hole 0.9: 1(-5,0) 2(5,0)
  silkscreen extent -3.5,-3 3.5,3, body extent -5.34,-3.02 5.34,3.02, height 11
Chemi-Con_1000x2000 [mm] "TH, 2-Leads, Body 10x20mm, Pin Spacing 5mm"
  rect 1.35x1.35 hole 0.85: 1(-2.5,0)
  round 1.35 hole 0.85: 2(2.5,0)
  silkscreen extent -5.25,-5.25 5.25,5.25, body extent -5.25,-5.25 5.25,5.25, height 21.5
D0007A_N [mm] "SOIC, 7-Leads, Body 4.9x3.9mm, Pitch 1.27mm, IPC Medium Density"
  oval 1.45x0.6 smd: 1(-2.725,1.905) 2(-2.725,0.635) 3(-2.725,-0.635) 4(-2.725,-1.905) 5(2.725,-1.905) 6(2.725,-0.635) 8(2.725,1.905)
  silkscreen extent -3.32,-2.5 1.1,2.52, body extent -3.01,-2.45 3.01,2.45, height 1.75
D0008A_N [mm] "SOIC, 8-Leads, Body 4.9x3.9mm, Pitch 1.27mm, IPC Medium Density"
  oval 1.45x0.6 smd: 1(-2.725,1.905) 2(-2.725,0.635) 3(-2.725,-0.635) 4(-2.725,-1.905) 5(2.725,-1.905) 6(2.725,-0.635) 7(2.725,0.635) 8(2.725,1.905)
  silkscreen extent -3.3,-2.5 0.9,2.5, body extent -3,-2.45 3,2.45, height 1.63
D0016A_N [mm] "SOIC, 16-Leads, Body 9.9x3.9mm, Pitch 1.27mm, IPC Medium Density"
  oval 1.45x0.6 smd: 1(-2.725,4.445) 2(-2.725,3.175) 3(-2.725,1.905) 4(-2.725,0.635) 5(-2.725,-0.635) 6(-2.725,-1.905) 7(-2.725,-3.175) 8(-2.725,-4.445) 9(2.725,-4.445) 10(2.725,-3.175) 11(2.725,-1.905) 12(2.725,-0.635) 13(2.725,0.635) 14(2.725,1.905) 15(2.725,3.175) 16(2.725,4.445)
  silkscreen extent -3.3,-5 0.9,5, body extent -3,-4.95 3,4.95, height 1.6
DBV0005A_N [mm] "SOT23, 5-Leads, Body 2.9x1.6mm, Pitch 0.95mm, Lead Span 2.8mm, IPC Medium Density"
  rrect17% 1x0.6 smd: 1(-1.375,0.95) 2(-1.375,0) 3(-1.375,-0.95) 4(1.375,-0.95) 5(1.375,0.95)
  silkscreen extent -1.63,-1.55 0.38,1.55, body extent -1.42,-1.46 1.42,1.46, height 1.09
DBV0006A_N [mm] "SOT23, 6-Leads, Body 2.9x1.6mm, Pitch 0.95mm, Lead Span 2.8mm, IPC Medium Density"
  rrect17% 1x0.6 smd: 1(-1.375,0.95) 2(-1.375,0) 3(-1.375,-0.95) 4(1.375,-0.95) 5(1.375,0) 6(1.375,0.95)
  silkscreen extent -1.68,-1.55 0.5,1.55, body extent -1.42,-1.46 1.42,1.46, height 1.12
DBZ0003A_N [mm] "SOT23, 3-Leads, Body 2.9x1.3mm, Pitch 0.95mm, Lead Span 2.4mm, IPC Medium Density"
  rrect17% 1x0.6 smd: 1(-1.2,0.95) 2(-1.2,-0.95) 3(1.2,0)
  silkscreen extent -1.65,-1.5 0.7,1.5, body extent -1.26,-1.46 1.26,1.46, height 0.98
DDB0014A [mm] "SMD, 14-Leads, Body 3.9x9.9mm, Pitch 1.27mm"
  rrect17% 1.55x0.6 smd: 1(-2.7,4.445) 3(-2.7,1.905) 4(-2.7,0.635) 5(-2.7,-0.635) 6(-2.7,-1.905) 7(-2.7,-3.175) 8(-2.7,-4.445) 9(2.7,-4.445) 10(2.7,-3.175) 11(2.7,-1.905) 12(2.7,-0.635) 14(2.7,1.905) 15(2.7,3.175) 16(2.7,4.445)
  silkscreen extent -3.5,-5 2,5, body extent -3.01,-4.95 3.01,4.95, height 1.75
DDPAK [mil] "D2-PAK, 3-Pads, Body 9.7x10.4mm (max), TO-263AB, using Vishay Silionix recommended pad sizes"
  rrect8% 135x49.49 smd: 1(-246.06,100) 3(-246.06,-100)
  rrect1% 355x420 smd paste-181.1: 4(155.51,0)
  silkscreen extent -295,-220 344,220, body extent -295,-202 324,202, height 180
DIP-4 [mm] "DIP, 4-Leads, Body 6.86x4.83mm, Pitch 2.54mm"
  rect 1.15x1.15 hole 0.65: 1(-3.81,1.27)
  round 1.15 hole 0.65: 2(-3.81,-1.27) 3(3.81,-1.27) 4(3.81,1.27)
  silkscreen extent -5.1,-2.41 3.43,2.41, body extent -4.02,-2.41 4.02,2.41, height 5.59
ESD_Overlay_Small [mil]
  silkscreen extent -62,-48 64,61
FCC_disclaimer [mil]
Fiducial10-20 [mm]
  round 1 smd mask+0.5: 1(0,0)
  Top Layer keep-out circle w1.178: c0,0 r0.5
GBU [mm] "Comchip / Diodes Inc diode bridge"
  round 2 hole 1.5: 1(-7.62,0) 2(-2.54,0) 3(2.54,0) 4(7.62,0)
  silkscreen extent -11.15,-2.28 11.15,1.28, body extent -11.15,-2.28 11.15,1.28, height 21.55
HEATSINK_782653B04250G [mil] "Aavid"
  round 210 hole 125: 1(-866.14,-275.59) 2(866.14,-275.59)
  silkscreen extent -984,-394 984,394, body extent -985,-395 985,395, height 512
"HEATSINK_782653B04250G - DUPLICATE1" [mil] "Aavid"
  round 210 hole 125: 1(-1358.27,-275.59) 2(1358.27,-275.59)
  silkscreen extent -1476,-394 1476,394, body extent -1476,-395 1476,395, height 512
IEC_HighVoltage_Small [mil]
  silkscreen extent -107,-88 107,97
IEC_HotSurface_Small [mil]
  silkscreen extent -107,-93 107,92
IND_7447020 [mm] "WURTH ELEKTRONIK"
  round 1.25 hole 0.75: 1(-3.5,0) 2(3.5,0)
  silkscreen extent -3.8,-7.9 3.8,7.9, body extent -3.8,-7.84 3.75,7.9, height 15.78
IND_CUST [mm]
  rect 2.159x2.159 hole 1.6: 1(-14,10)
  round 2.159 hole 1.6: 2(-14,-10) 6(14,-10) 7(14,-5) 8(14,0) 9(14,5) 10(14,10)
  silkscreen extent -16,-15 16,15, body extent -16,-15 16,14.97, height 13
Keystone5000 [mil] "For Keystone 500x miniature loop terminals"
  round 80 hole 40: 1(0,0)
  silkscreen extent -52,-52 52,52, body extent -49,-49 49,49, height 182
Keystone5001 [mil] "For Keystone 500x miniature loop terminals"
  round 80 hole 40: 1(0,0)
  silkscreen extent -52,-52 52,52, body extent -49,-49 49,49, height 182
KXG_1800X4000_HORIZONTALDOWN [mm] "TH, 2-Leads, Dia 18mm, Pin Spacing 7.5mm"
  rect 1.55x1.55 hole 1.05: 1(3.75,0)
  round 1.55 hole 1.05: 2(-3.75,0)
  silkscreen extent -9.25,-43.65 9.25,-2.15, body extent -9.26,-43.65 9.25,0.4, height 18.5
KXG_1800x4000_horizontalDown [mm] "TH, 2-Leads, Dia 18mm, Pin Spacing 7.5mm"
  rect 1.55x1.55 hole 1.05: 1(-3.75,0)
  round 1.55 hole 1.05: 2(3.75,0)
  silkscreen extent -9.25,-43.65 9.25,-2.15, body extent -9.26,-43.65 9.25,0.4, height 18.5
LITTELFUSE_01110501Z [mm] "FUSE CLIP, CARTRIDGE, 250V, 10A, PCB"
  rect 1.67x1.67 / inner round 1.67 / far side rect 1.67x1.67 hole 1.17: 1(-8.9,2.5)
  round 1.67 hole 1.17: 2(-8.9,-2.5) 3(8.9,2.5) 4(8.9,-2.5)
  Top Layer keep-out region: -11.3,-1.501 -6.5,-1.501 -6.5,1.499 -11.3,1.499
  Top Layer keep-out region: 6.5,-1.501 11.3,-1.501 11.3,1.499 6.5,1.499
  silkscreen extent -11.3,-2.66 11.3,3.77, body extent -11.3,-2.66 11.3,2.66, height 7.1
MPK_1800x650 [mm] "TH, 2-Leads, Body 18x6.5mm, Lead Spacing 15mm"
  round 1.35 hole 0.85: 1(-7.5,0) 2(7.5,0)
  silkscreen extent -9,-3.25 9,3.25, body extent -9,-3.25 9,3.25, height 12
MPK_1800x950 [mm] "TH, 2-Leads, Body 18x9.5mm, Lead Spacing 15mm"
  round 1.55 hole 1.05: 1(-7.5,0) 2(7.5,0)
  silkscreen extent -9,-4.75 9,4.75, body extent -9,-4.75 9,4.75, height 14
Pb-Free_Overlay_Small [mil]
  silkscreen extent -46,-46 46,46
PK0003A_M [mm] "SOT89, 3-Leads, Body 4.5x2.5mm, Pitch 1.5mm, IPC Low Density"
  rrect14% 1.6x0.7 smd: 1(-0.025,1.5) 3(-0.025,-1.5)
  rrect14% 1.7x0.7 smd: 2(0.025,0)
  Top Layer region: 0.875,0.35 1.525,1 3.925,1 4.575,0.35 4.575,-0.35 3.925,-1 1.525,-1 0.875,-0.35 0.675,-0.35 0.675,0.35
  silkscreen extent -0.62,-2.3 3.53,2.3, body extent -0.26,-2.25 3.84,2.25, height 1.6
SMA [mm] "Molded Diode, 2-Leads, Body 4.3x2.6mm, IPC Medium Density, based on OnSemi component dimensions and land pattern"
  rect 2x2 smd: 1(-2,0) 2(2,0)
  silkscreen extent -3.66,-1.57 2.79,1.57, body extent -2.6,-1.3 2.6,1.3, height 2.42
SMB [mil] "Molded Diode, 2-Leads, Body 5.4x3.6mm, IPC Medium Density, based on OnSemi component dimensions"
  rect 85x107.99 smd: 1(-87.01,0) 2(87.01,0)
  silkscreen extent -155,-82 125,82, body extent -106,-71 106,71, height 91
SOD-123 [mm] "On Semi recommended land pattern"
  rect 0.915x1.22 smd: 1(-1.637,0) 2(1.637,0)
  silkscreen extent -2.74,-1.17 2.03,1.17, body extent -1.93,-0.9 1.93,0.9, height 1.35
SOD-123FL [mm] "Copied from SOD-123"
  rect 0.915x1.22 smd: 1(-1.637,0) 2(1.637,0)
  silkscreen extent -2.74,-1.16 1.68,1.16, body extent -1.9,-0.9 1.9,0.9, height 1
sod-323 [mm] "NXP recommended land pattern"
  rect 0.6x0.6 smd paste-0.05: 1(-1.1,0) 2(1.1,0)
  silkscreen extent -2.06,-0.86 1.53,0.86, body extent -1.3,-0.67 1.3,0.68, height 1.1
SOD-323 [mm] "NXP recommended land pattern"
  rect 0.6x0.6 smd paste-0.05: 1(-1.1,0) 2(1.1,0)
  silkscreen extent -2.06,-0.86 1.53,0.86, body extent -1.3,-0.67 1.3,0.68, height 1.1
SOD-523 [mm] "NXP Semiconductor recommended land pattern, nominal STEP model"
  rect 0.8x0.6 smd paste-0.05: 1(-0.55,0) 2(0.55,0)
  silkscreen extent -1.65,-0.66 1.2,0.66, body extent -0.8,-0.4 0.8,0.4, height 0.72
SOD-523F [mm] "COMCHIP"
  rect 0.6x0.8 smd paste-0.05: 1(-0.85,0) 2(0.85,0)
  silkscreen extent -1.93,-0.87 1.1,0.88, body extent -0.9,-0.5 0.9,0.5, height 0.85
SOT-23 [mm] "SOT23, 3-Leads, Body 2.9x1.3mm, Pitch 0.95mm, Lead Span 2.5mm, IPC Medium Density"
  rrect50% 1x0.6 smd: 1(-1.2,0.95) 2(-1.2,-0.95) 3(1.2,0)
  silkscreen extent -1.63,-1.5 0.7,1.5, body extent -1.16,-1.45 1.21,1.45, height 1
TE_350429-1 [mm] "Header(Shrouded), 6.35mm, 3x1, TH"
  rect 2.3x2.3 hole 1.78: 1(-6.35,0)
  round 2.3 hole 1.78: 2(0,0) 3(6.35,0)
  silkscreen extent -10.16,-5.08 10.16,4.5, body extent -12.7,-5.08 12.7,3.81, height 14.83
TERM_BLK_OSTT7022150 [mm]
  rect 2.54x2.54 hole 1.6: 1(0,0)
  round 2.54 hole 1.6: 2(9.525,0)
  silkscreen extent -5.74,-8.28 14.63,4.83, body extent -5.45,-8 14.32,5.35, height 21.6
THCBR1290 [mm] "Delta Electronics"
  round 1.8 hole 1.3: 1(-5.25,0) 2(5.25,0)
  silkscreen extent -4.9,-4.5 4.9,4.5, body extent -4.9,-4.5 4.9,4.5, height 9.2
THERM_B57236S0 [mm] "EPCOS"
  round 1.35 hole 0.85: 1(-2.5,0) 2(2.5,0)
  silkscreen extent -5.75,-3 5.75,3, body extent -5.75,-3 5.7,3, height 15.99
TI_Stacked_Overlay_Small [mil]
  silkscreen extent -418,-98 418,98
TO-220AB_HORIZONTAL#1 [mil] "For SolarMagic, with tab facing heatsink, away from PCB"
  round 75 hole 50: 1(100,0) 2(0,-93) 3(-100,0)
  silkscreen extent -210,79 210,800, body extent -210,-12 210,800, height 192
TO-220AB_HORIZONTAL#2 [mil] "For SolarMagic, with tab facing heatsink, away from PCB"
  rrect5% 76x118.11 hole 50: 1(100,0)
  rrect100% 76x118.11 hole 50: 2(0,0) 3(-100,0)
  silkscreen extent -210,79 210,800, body extent -210,-12 210,800, height 192
TO-220AC_HORIZ [mil]
  rect 70x70 hole 47: 1(100,0)
  round 70 hole 47: 3(-100,0)
  body extent -210,200 209,800, height 180
VAR_S10K275E2 [mm] "EPCOS"
  round 1.6 hole 1.1: 1(-3.75,1.1) 2(3.75,-1.1)
  silkscreen extent -6,-2.7 6,2.7, body extent -5.98,-2.7 5.98,2.7, height 14.99
WE-CMBH [mm] "THT Inductor, 4-Leads, Body 28 x 32.5mm"
  rect 2x2 hole 1.2: 1(-6.25,13.75)
  round 2 hole 1.2: 2(-6.25,-13.75) 3(6.25,-13.75) 4(6.25,13.75)
  silkscreen extent -14,-16.25 14,17, body extent -13.83,-16.25 13.83,16.25, height 20
WE-CMBH_UPDATED [mm] "THT Inductor, 4-Leads, Body 28 x 32.5mm"
  rect 2x2 hole 1.2: 1(-7.45,-16.175)
  round 2 hole 1.2: 2(7.4,-16.175) 3(7.525,16.25) 4(-7.375,16.25)
  silkscreen extent -15.5,-18.28 15.5,17.5, body extent -13.83,-16.25 13.83,16.25, height 20
WE-TI_5075 [mm] "Wurth WE-TI 5075"
  rect 1.4x1.4 hole 0.787: 1(-1.25,0)
  round 1.4 hole 0.787: 2(1.25,0)
  silkscreen extent -3,-3 3,3, body extent -3,-3 3,3, height 8.5
WE_750343661_CUS [mil] "TRANSFORMER, TH, 14-PIN"
  rect 130x130 hole 110.24: 1(-1000,600)
  round 130 hole 110.24: 2(-1000,450) 6(-1000,-450) 7(-1000,-600)
  round 140 hole 118.11: 8(800,-450) 10(800,-225) 11(800,225) 13(800,450)
  silkscreen extent -1085,-825 884,805, body extent -1085,-825 885,805, height 598

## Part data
C1 C70: "CAP, AL, 150 µF, 450 V, +/- 20%, TH", Cap_Case=18x45mm, Manufacturer=Rubycon, Supplier Part Number 1=1189-1353-ND, Tolerance_%=20, Value2=450V, ValueDisplayed=150µF
C2 C3: library part B32652A7153J000, "CAP FILM 0.033UF 5% 1KVDC RADIAL", Cap_Case=18x7x12.5, Manufacturer=TDK, Supplier Part Number 1=495-7142-ND, Tolerance_%=5, Value2=1250V, ValueDisplayed=0.033µF
C4: "CAP, Film, 0.47 µF, 450 V, +/- 5%, TH", Cap_Case=18x6.5mm, Manufacturer=Rubycon, Supplier Part Number 1=1189-1824-ND, Tolerance_%=5, Value1=Unknown, Value2=450V, ValueDisplayed=0.47µF
C5: "CAP, Film, 1 µF, 450 V, +/- 5%, TH", Cap_Case=18x9.5mm, Manufacturer=Rubycon, Supplier Part Number 1=1189-1822-ND, Tolerance_%=5, Value1=Unknown, Value2=450V, ValueDisplayed=1µF
C6 C8 C11: "CAP, CERM, 2200 pF, 300 V, +/- 20%, Y5U, AEC-Q200 Grade 1, D9.5xT5mm", Cap_Case=9.5x5mm, Manufacturer=Vishay-Bccomponents, Supplier Part Number 1=BC2914-ND, TempCo=Y5U, Tolerance_%=20, Value1=Unknown, Value2=300V, ValueDisplayed=2200pF
C7 C21 C38: "CAP, CERM, 0.1 µF, 16 V, +/- 10%, X7R, 0603", Cap_Case=0603, Manufacturer="Taiyo Yuden", Supplier Part Number 1=587-1240-1-ND, TempCo=X7R, Tolerance_%=10, Value1=Unknown, Value2=16V, ValueDisplayed=0.1µF
C9 C10 C51 C52: "CAP, Film, 0.33 µF, X2 305 VAC, +/- 10%, TH", Cap_Case=18x8x14.5mm, Manufacturer=TDK, Supplier Part Number 1=495-5051-ND, Tolerance_%=10, ValueDisplayed=0.33µF
C12 C13 C14 C76 C77: library part EKZE350ELL471MJ20S, "CAP, AL, 330 µF, 35 V, +/- 20%, TH", Cap_Case=10x20, Manufacturer=Rubycon, Supplier Part Number 1=1189-1891-ND, Tolerance_%=20, Value2=35V, ValueDisplayed=330µF
C15 C69: "CAP, CERM, 470 pF, 500 V, +/- 10%, X7R, 1210", Cap_Case=1210, Manufacturer=Vishay-Vitramon, Supplier Part Number 1=720-1054-1-ND, TempCo=X7R, Tolerance_%=10, Value1=Unknown, Value2=500V, ValueDisplayed=470pF
C16 C35: "CAP, CERM, 4.7 µF, 10 V, +/- 10%, X5R, 0603", Cap_Case=0603, Manufacturer=AVX, Supplier Part Number 1=478-7943-1-ND, TempCo=X5R, Tolerance_%=10, Value1=Unknown, Value2=10V, ValueDisplayed=4.7µF
C17: "CAP, CERM, 0.01 µF, 100 V, +/- 5%, X7R, 0603", Cap_Case=0603, Manufacturer=AVX, Supplier Part Number 1=478-3700-1-ND, TempCo=X7R, Tolerance_%=5, Value1="0.098 ohm", Value2=100V, ValueDisplayed=0.01µF
C18: "CAP, CERM, 100 pF, 50 V, +/- 5%, C0G/NP0, 0603", Cap_Case=0603, Manufacturer=Kemet, Supplier Part Number 1=1414602, TempCo=C0G/NP0, Tolerance_%=5, Value1=Unknown, Value2=50V, ValueDisplayed=100pF
C19: "CAP, CERM, 3.3 pF, 50 V, +/- 8%, C0G/NP0, 0805", Cap_Case=0805, Manufacturer=AVX, Supplier Part Number 1=478-1298-1-ND, TempCo=C0G/NP0, Tolerance_%=8, Value1="3.467 ohm", Value2=50V, ValueDisplayed=3.3pF
C20: "CAP, CERM, 10 pF, 50 V, +/- 5%, C0G/NP0, 0603", Cap_Case=0603, Manufacturer=AVX, Supplier Part Number 1=478-1163-1-ND, TempCo=C0G/NP0, Tolerance_%=5, Value1="0.403 ohm", Value2=50V, ValueDisplayed=10pF
C22: "CAP, CERM, 6800 pF, 50 V, +/- 10%, X7R, 0603", Cap_Case=0603, Manufacturer=MuRata, Supplier Part Number 1=490-1508-1-ND, TempCo=X7R, Tolerance_%=10, Value1=Unknown, Value2=50V, ValueDisplayed=6800pF
C23 C36: "CAP, CERM, 2.2 µF, 16 V, +/- 10%, X5R, 0805", Cap_Case=0805, Manufacturer=AVX, Supplier Part Number 1=478-2580-1-ND, TempCo=X5R, Tolerance_%=10, Value1="0.009 ohm", Value2=16V, ValueDisplayed=2.2µF
C24 C25: "CAP, CERM, 22 pF, 50 V, +/- 5%, C0G/NP0, 0603", Cap_Case=0603, Manufacturer=Kemet, Supplier Part Number 1=399-1053-1-ND, TempCo=C0G/NP0, Tolerance_%=5, Value1=Unknown, Value2=50V, ValueDisplayed=22pF
C26: "CAP, CERM, 0.1 µF, 100 V,+/- 10%, X7R, 0805", Cap_Case=0805, Manufacturer=Kemet, Supplier Part Number 1=399-3486-1-ND, TempCo=X7R, Tolerance_%=10, Value1="0.064 ohm", Value2=100V, ValueDisplayed=0.1µF
C27: "CAP, CERM, 10 µF, 10 V, +/- 20%, X5R, 0603", Cap_Case=0603, Manufacturer=TDK, Supplier Part Number 1=445-6853-1-ND, TempCo=X5R, Tolerance_%=20, Value1="0.0078 ohm", Value2=10V, ValueDisplayed=10µF
C28: "CAP, CERM, 0.1 µF, 16 V, +/- 5%, X7R, 0603", Cap_Case=0603, Manufacturer=AVX, Supplier Part Number 1=478-3726-1-ND, TempCo=X7R, Tolerance_%=5, Value1="0.039 ohm", Value2=16V, ValueDisplayed=0.1µF
C29 C33: "CAP, CERM, 1000 pF, 50 V, +/- 10%, X7R, 0603", Cap_Case=0603, Manufacturer=TDK, Supplier Part Number 1=445-1308-1-ND, TempCo=X7R, Tolerance_%=10, Value1="0.24 ohm", Value2=50V, ValueDisplayed=1000pF
C30 C60 C61 C62: "CAP, CERM, 1 µF, 25 V, +/- 10%, X7R, 0603", Cap_Case=0603, Manufacturer=MuRata, Supplier Part Number 1=490-5307-1-ND, TempCo=X7R, Tolerance_%=10, Value1=Unknown, Value2=25V, ValueDisplayed=1µF
C31: "CAP, CERM, 0.22 µF, 25 V, +/- 10%, X5R, 0603", Cap_Case=0603, Manufacturer=AVX, Supplier Part Number 1=478-1245-1-ND, TempCo=X5R, Tolerance_%=10, Value1="0.036 ohm", Value2=25V, ValueDisplayed=0.22µF
C32: "CAP, CERM, 0.1 µF, 100 V, +/- 10%, X7R, 0603", Cap_Case=0603, Manufacturer=MuRata, Supplier Part Number 1=490-6439-1-ND, TempCo=X7R, Tolerance_%=10, Value1=Unknown, Value2=100V, ValueDisplayed=0.1µF
C34: "CAP, CERM, 820 pF, 50 V, +/- 5%, C0G/NP0, 0603", Cap_Case=0603, Manufacturer=AVX, Supplier Part Number 1=478-1186-1-ND, TempCo=C0G/NP0, Tolerance_%=5, Value1="0.052 ohm", Value2=50V, ValueDisplayed=820pF
C37: "CAP, CERM, 1 µF, 50 V, +/- 10%, X7R, 0603", Cap_Case=0603, Manufacturer="Taiyo Yuden", Supplier Part Number 1=587-3247-1-ND, TempCo=X7R, Tolerance_%=10, Value1=Unknown, Value2=50V, ValueDisplayed=1µF
C39 C40: "CAP, CERM, 150 pF, 1000 V, +/- 5%, U2J, 1206", Cap_Case=1206, Manufacturer=MuRata, Supplier Part Number 1=490-4302-1-ND, TempCo=U2J, Tolerance_%=5, Value1=Unknown, Value2=1000V, ValueDisplayed=150pF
